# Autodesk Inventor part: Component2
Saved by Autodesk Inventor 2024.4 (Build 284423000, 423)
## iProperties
Created: 2025-04
Part Number: Component2
Material: Generic
Document SubType Name: Modeling
Designer: AdminForWorker
Density: 1 g/cm^3
Appearance: Default
Title: Component2
Author: AdminForWorker
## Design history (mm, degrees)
